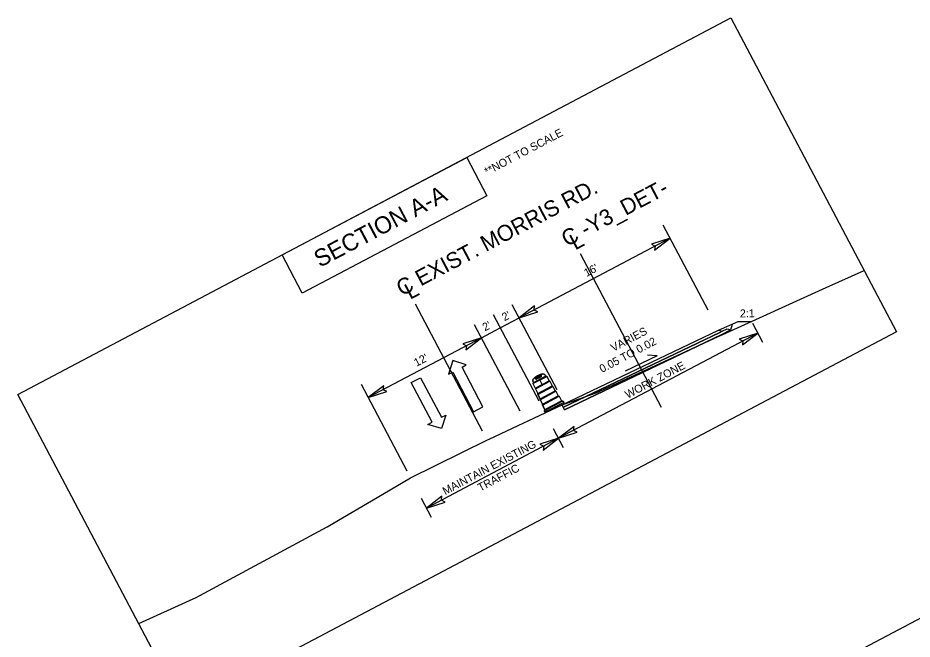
# Model space of a CAD drawing. Extents: x 1487176 to 1495274, y 497106 to 503692.
# Drawn here: x 1488601.9 to 1488685.7, y 497344.5 to 497402.7 of the extents above; entities that cross this region are included whole.
import ezdxf

# ---------------------------------------------------------------- set-up
doc = ezdxf.new("R2010")
doc.units = 0
for name, color, linetype in [('Default', 7, 'Continuous'), ('Exist XS Ground Line', 7, 'Continuous'), ('Prop Terminator CELL', 7, 'Continuous'), ('Typical Hinge Slope Interstate CELL', 7, 'Continuous'), ('Typical Pavement Slope Information CELL', 7, 'Continuous'), ('WZ OSDR CELL', 7, 'Continuous')]:
    doc.layers.add(name, color=color, linetype=linetype)

msp = doc.modelspace()

# ---------------------------------------------------------------- linework, layer by layer
at = {"layer": 'Default'}
for p, q in [((1488666.617, 497375.311), (1488662.406, 497383.285)), ((1488663.053, 497382.06), (1488648.904, 497374.589)), ((1488662.248, 497366.187), (1488654.647, 497380.582)), ((1488645.463, 497363.972), (1488639.178, 497375.875)), ((1488652.468, 497367.84), (1488648.257, 497375.814)), ((1488650.769, 497366.774), (1488646.489, 497374.88)), ((1488647.135, 497373.656), (1488648.904, 497374.589)), ((1488649, 497365.84), (1488644.72, 497373.946)), ((1488645.367, 497372.722), (1488647.135, 497373.656)), ((1488671.75, 497372.287), (1488670.816, 497374.056)), ((1488645.367, 497372.722), (1488634.755, 497367.119)), ((1488671.283, 497373.171), (1488652.6, 497363.306)), ((1488642.683, 497370.583), (1488642.276, 497369.299)), ((1488643.947, 497370.182), (1488642.683, 497370.583)), ((1488643.549, 497369.972), (1488643.947, 497370.182)), ((1488642.276, 497369.299), (1488642.674, 497369.509)), ((1488642.674, 497369.509), (1488644.635, 497365.795)), ((1488645.51, 497366.258), (1488643.549, 497369.972)), ((1488638.781, 497368.523), (1488639.656, 497368.985)), ((1488640.742, 497364.809), (1488638.781, 497368.523)), ((1488639.656, 497368.985), (1488641.617, 497365.271)), ((1488638.389, 497360.237), (1488634.108, 497368.343)), ((1488644.635, 497365.795), (1488645.51, 497366.258)), ((1488653.168, 497365.987), (1488652.935, 497366.429)), ((1488641.617, 497365.271), (1488642.015, 497365.481)), ((1488642.015, 497365.481), (1488641.634, 497364.211)), ((1488640.344, 497364.599), (1488640.742, 497364.809)), ((1488641.634, 497364.211), (1488640.344, 497364.599)), ((1488653.067, 497362.422), (1488652.133, 497364.19)), ((1488652.6, 497363.306), (1488640.22, 497356.769)), ((1488640.687, 497355.885), (1488639.753, 497357.653))]:
    msp.add_line(p, q, dxfattribs=at)
for points in [[(1488601.91, 497367.406), (1488668.759, 497402.704), (1488684.294, 497373.283), (1488617.445, 497337.985)], [(1488626.677, 497380.484), (1488643.991, 497389.626), (1488645.884, 497386.042), (1488628.57, 497376.899)], [(1488616.644, 497309.569), (1488708.211, 497357.918), (1488723.746, 497328.497), (1488632.179, 497280.148)]]:
    msp.add_lwpolyline(points, close=True, dxfattribs=at)
for points in [[(1488667.603, 497373.443), (1488669.446, 497374.235)], [(1488667.72, 497373.222), (1488667.948, 497373.336), (1488668.394, 497373.561), (1488668.739, 497373.454)], [(1488668.739, 497373.454), (1488668.909, 497374.004)], [(1488669.446, 497374.235), (1488670.707, 497374.263)], [(1488652.935, 497366.429), (1488667.603, 497373.443)], [(1488652.935, 497366.429), (1488667.603, 497373.443)], [(1488652.935, 497366.429), (1488667.603, 497373.443)], [(1488667.72, 497373.222), (1488653.051, 497366.208)], [(1488653.051, 497366.208), (1488667.72, 497373.222)], [(1488653.168, 497365.987), (1488667.836, 497373)], [(1488667.836, 497373), (1488653.168, 497365.987)], [(1488667.603, 497373.443), (1488667.603, 497373.443)], [(1488667.603, 497373.443), (1488667.603, 497373.443)], [(1488667.603, 497373.443), (1488667.948, 497373.336)], [(1488667.948, 497373.336), (1488667.72, 497373.222)], [(1488668.739, 497373.454), (1488667.836, 497373)], [(1488667.836, 497373), (1488668.739, 497373.454)]]:
    msp.add_lwpolyline(points, dxfattribs=at)
at = {"layer": 'Exist XS Ground Line'}
msp.add_lwpolyline([(1488613.237, 497345.954), (1488617.992, 497348.095), (1488618.621, 497348.392), (1488618.982, 497348.576), (1488630.909, 497355.017), (1488636.138, 497358.073), (1488638.731, 497359.589), (1488645.873, 497363.118), (1488646.159, 497363.254), (1488652.935, 497366.429), (1488656.133, 497367.571), (1488664.115, 497371.252), (1488667.562, 497372.854), (1488668.007, 497373.038), (1488677.674, 497377.424), (1488681.252, 497379.043)], dxfattribs=at)
at = {"layer": 'Prop Terminator CELL'}
for points in [[(1488661.606, 497380.946), (1488663.053, 497382.06), (1488661.303, 497381.498), (1488661.655, 497381.322)], [(1488650.351, 497375.704), (1488648.904, 497374.589), (1488650.654, 497375.152), (1488650.301, 497375.327)], [(1488643.92, 497371.607), (1488645.367, 497372.722), (1488643.617, 497372.16), (1488643.97, 497371.984)], [(1488669.836, 497372.057), (1488671.283, 497373.171), (1488669.533, 497372.609), (1488669.886, 497372.434)], [(1488636.202, 497368.233), (1488634.755, 497367.119), (1488636.505, 497367.681), (1488636.152, 497367.856)], [(1488654.047, 497364.421), (1488652.6, 497363.306), (1488654.35, 497363.868), (1488653.997, 497364.044)], [(1488651.153, 497362.192), (1488652.6, 497363.306), (1488650.85, 497362.744), (1488651.203, 497362.568)], [(1488641.667, 497357.884), (1488640.22, 497356.769), (1488641.97, 497357.331), (1488641.617, 497357.507)]]:
    msp.add_lwpolyline(points, close=True, dxfattribs=at)
at = {"layer": 'Typical Pavement Slope Information CELL'}
for q in [(1488658.854, 497369.595), (1488660.934, 497371.096)]:
    msp.add_line((1488661.846, 497371.025), q, dxfattribs=at)
at = {"layer": 'WZ OSDR CELL'}
for p, q in [((1488650.256, 497368.546), (1488650.187, 497368.675)), ((1488650.198, 497368.427), (1488651.494, 497369.111)), ((1488650.256, 497368.546), (1488651.364, 497369.131)), ((1488650.418, 497368.011), (1488651.714, 497368.695)), ((1488650.423, 497367.925), (1488651.782, 497368.643)), ((1488650.442, 497368.863), (1488650.439, 497368.869)), ((1488650.997, 497369.155), (1488650.994, 497369.161)), ((1488651.364, 497369.131), (1488651.296, 497369.26)), ((1488651.494, 497369.111), (1488651.714, 497368.695)), ((1488651.714, 497368.695), (1488651.782, 497368.643)), ((1488651.782, 497368.643), (1488652.001, 497368.227)), ((1488650.198, 497368.427), (1488650.418, 497368.011)), ((1488650.418, 497368.011), (1488650.423, 497367.925)), ((1488650.423, 497367.925), (1488650.642, 497367.509)), ((1488650.642, 497367.509), (1488652.001, 497368.227)), ((1488650.648, 497367.424), (1488652.069, 497368.174)), ((1488650.867, 497367.008), (1488652.289, 497367.759)), ((1488650.872, 497366.922), (1488652.357, 497367.706)), ((1488652.001, 497368.227), (1488652.069, 497368.174)), ((1488652.069, 497368.174), (1488652.289, 497367.759)), ((1488652.289, 497367.759), (1488652.357, 497367.706)), ((1488652.357, 497367.706), (1488652.576, 497367.29)), ((1488650.642, 497367.509), (1488650.648, 497367.424)), ((1488650.648, 497367.424), (1488650.867, 497367.008)), ((1488650.867, 497367.008), (1488650.872, 497366.922)), ((1488650.872, 497366.922), (1488651.092, 497366.506)), ((1488651.092, 497366.506), (1488652.576, 497367.29)), ((1488651.097, 497366.421), (1488652.644, 497367.238)), ((1488651.316, 497366.005), (1488652.864, 497366.822)), ((1488652.576, 497367.29), (1488652.644, 497367.238)), ((1488652.644, 497367.238), (1488652.864, 497366.822)), ((1488652.864, 497366.822), (1488652.932, 497366.769)), ((1488651.092, 497366.506), (1488651.097, 497366.421)), ((1488651.097, 497366.421), (1488651.316, 497366.005)), ((1488651.312, 497365.914), (1488652.941, 497366.774)), ((1488651.316, 497365.739), (1488653.083, 497366.672)), ((1488651.317, 497366.005), (1488651.322, 497365.919)), ((1488653.083, 497366.672), (1488653.047, 497366.741)), ((1488651.316, 497365.739), (1488651.28, 497365.808))]:
    msp.add_line(p, q, dxfattribs=at)
for points in [[(1488651.782, 497368.643), (1488651.102, 497368.284), (1488650.736, 497368.977), (1488650.795, 497369.007), (1488650.837, 497369.025), (1488650.873, 497369.042), (1488650.904, 497369.054), (1488650.938, 497369.068), (1488650.967, 497369.078), (1488650.98, 497369.084), (1488650.99, 497369.092), (1488650.998, 497369.107), (1488651.002, 497369.122), (1488651.003, 497369.136), (1488651, 497369.148), (1488650.994, 497369.161), (1488650.983, 497369.176), (1488650.968, 497369.185), (1488650.957, 497369.189), (1488650.946, 497369.19), (1488650.937, 497369.19), (1488650.927, 497369.187), (1488650.902, 497369.178), (1488650.877, 497369.169), (1488650.852, 497369.159), (1488650.826, 497369.149), (1488650.794, 497369.135), (1488650.759, 497369.119), (1488650.732, 497369.107), (1488650.709, 497369.095), (1488650.682, 497369.081), (1488650.636, 497369.168), (1488650.676, 497369.189), (1488650.709, 497369.204), (1488650.755, 497369.225), (1488650.786, 497369.239), (1488650.822, 497369.253), (1488650.862, 497369.269), (1488650.91, 497369.285), (1488650.958, 497369.3), (1488651.016, 497369.316), (1488651.065, 497369.328), (1488651.107, 497369.337), (1488651.127, 497369.341), (1488651.146, 497369.344), (1488651.167, 497369.344), (1488651.189, 497369.341), (1488651.205, 497369.336), (1488651.225, 497369.328), (1488651.242, 497369.319), (1488651.259, 497369.307), (1488651.272, 497369.295), (1488651.284, 497369.279), (1488651.292, 497369.266), (1488651.296, 497369.26), (1488651.364, 497369.131), (1488651.396, 497369.132), (1488651.413, 497369.131), (1488651.431, 497369.129), (1488651.451, 497369.126), (1488651.474, 497369.119), (1488651.486, 497369.115), (1488651.494, 497369.111), (1488651.714, 497368.695)], [(1488650.423, 497367.925), (1488651.102, 497368.284), (1488650.736, 497368.977), (1488650.703, 497368.959), (1488650.678, 497368.944), (1488650.652, 497368.93), (1488650.625, 497368.913), (1488650.597, 497368.895), (1488650.568, 497368.875), (1488650.536, 497368.853), (1488650.516, 497368.839), (1488650.502, 497368.834), (1488650.489, 497368.833), (1488650.475, 497368.836), (1488650.464, 497368.841), (1488650.454, 497368.848), (1488650.446, 497368.856), (1488650.436, 497368.875), (1488650.433, 497368.886), (1488650.434, 497368.902), (1488650.438, 497368.915), (1488650.446, 497368.93), (1488650.455, 497368.938), (1488650.479, 497368.955), (1488650.51, 497368.977), (1488650.576, 497369.021), (1488650.625, 497369.049), (1488650.662, 497369.07), (1488650.682, 497369.081), (1488650.636, 497369.168), (1488650.6, 497369.149), (1488650.554, 497369.122), (1488650.508, 497369.094), (1488650.46, 497369.062), (1488650.416, 497369.031), (1488650.368, 497368.995), (1488650.315, 497368.951), (1488650.284, 497368.924), (1488650.236, 497368.879), (1488650.215, 497368.859), (1488650.203, 497368.846), (1488650.191, 497368.828), (1488650.181, 497368.809), (1488650.173, 497368.783), (1488650.169, 497368.76), (1488650.169, 497368.74), (1488650.172, 497368.719), (1488650.177, 497368.699), (1488650.187, 497368.675), (1488650.256, 497368.546), (1488650.246, 497368.534), (1488650.237, 497368.52), (1488650.225, 497368.501), (1488650.215, 497368.48), (1488650.207, 497368.46), (1488650.198, 497368.427), (1488650.418, 497368.011)], [(1488650.642, 497367.509), (1488652.001, 497368.227), (1488652.069, 497368.174), (1488652.289, 497367.759), (1488652.357, 497367.706), (1488650.872, 497366.922), (1488650.867, 497367.008), (1488650.648, 497367.424)], [(1488651.092, 497366.506), (1488652.576, 497367.29), (1488652.644, 497367.238), (1488652.864, 497366.822), (1488652.932, 497366.769), (1488652.949, 497366.778), (1488652.961, 497366.781), (1488652.977, 497366.783), (1488652.993, 497366.782), (1488653.004, 497366.779), (1488653.017, 497366.773), (1488653.029, 497366.764), (1488653.037, 497366.756), (1488653.043, 497366.748), (1488653.047, 497366.741), (1488653.083, 497366.672), (1488651.316, 497365.739), (1488651.28, 497365.808), (1488651.275, 497365.819), (1488651.272, 497365.831), (1488651.271, 497365.843), (1488651.271, 497365.855), (1488651.273, 497365.864), (1488651.278, 497365.879), (1488651.286, 497365.891), (1488651.295, 497365.902), (1488651.302, 497365.908), (1488651.312, 497365.914), (1488651.322, 497365.919), (1488651.317, 497366.005), (1488651.097, 497366.421)]]:
    msp.add_lwpolyline(points, close=True, dxfattribs=at)
for centre, radius, start, end in [((1488651.462, 497367.604), 1.769, 100.88588, 134.78432), ((1488651.157, 497369.187), 0.157, 27.8351, 100.88588), ((1488650.326, 497368.748), 0.157, 134.78432, 207.8351), ((1488650.463, 497368.372), 0.271, 140.14111, 168.34864), ((1488650.488, 497368.894), 0.0548, 126.50911, 207.8351), ((1488650.491, 497368.888), 0.0548, 207.8351, 305.98385), ((1488651.508, 497367.516), 1.769, 109.16109, 126.50911), ((1488651.563, 497367.412), 1.769, 109.68635, 125.98385), ((1488650.945, 497369.136), 0.0548, 27.8351, 109.16109), ((1488650.948, 497369.13), 0.0548, 289.68635, 27.8351), ((1488651.39, 497368.861), 0.271, 67.32155, 95.52908), ((1488652.977, 497366.705), 0.0783, 27.8351, 117.8351), ((1488651.349, 497365.845), 0.0783, 117.8351, 207.8351)]:
    msp.add_arc(centre, radius, start, end, dxfattribs=at)

# ---------------------------------------------------------------- texts
at = {"layer": 'Default'}
for s, height, rotation, p in [('**NOT TO SCALE', 0.75, 27.83509, (1488645.886, 497387.91)), ('SECTION A-A', 1.6, 27.83509, (1488630.21, 497379.274)), ("16'", 0.75, 27.83509, (1488655.225, 497378.42)), ("2'", 0.75, 27.83509, (1488647.524, 497374.263)), ('2:1', 0.75, 1.27004, (1488669.603, 497374.628)), ("2'", 0.75, 27.83509, (1488645.701, 497373.32)), ('VARIES ', 0.75, 27.83509, (1488657.732, 497371.396)), ('0.05 TO 0.02', 0.75, 27.83509, (1488656.671, 497369.422)), ("12'", 0.75, 27.83509, (1488639.278, 497370)), ('WORK ZONE', 0.75, 27.83509, (1488659.078, 497367.004)), ('MAINTAIN EXISTING', 0.75, 27.83509, (1488641.966, 497357.969)), ('TRAFFIC', 0.75, 27.83509, (1488645.26, 497358.295))]:
    msp.add_text(s, height=height, rotation=rotation, dxfattribs=at).set_placement(p)
at = {"layer": 'Typical Hinge Slope Interstate CELL'}
for s, p in [('C EXIST. MORRIS RD.', (1488637.894, 497376.592)), ('C -Y3_DET- ', (1488653.368, 497381.224)), ('L', (1488654.149, 497380.903)), ('L', (1488638.675, 497376.271))]:
    msp.add_text(s, height=1.5, rotation=27.83509, dxfattribs=at).set_placement(p)

doc.saveas('drawing.dxf')
